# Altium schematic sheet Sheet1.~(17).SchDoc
size A4; SheetNumber: 1; SheetTotal: 1
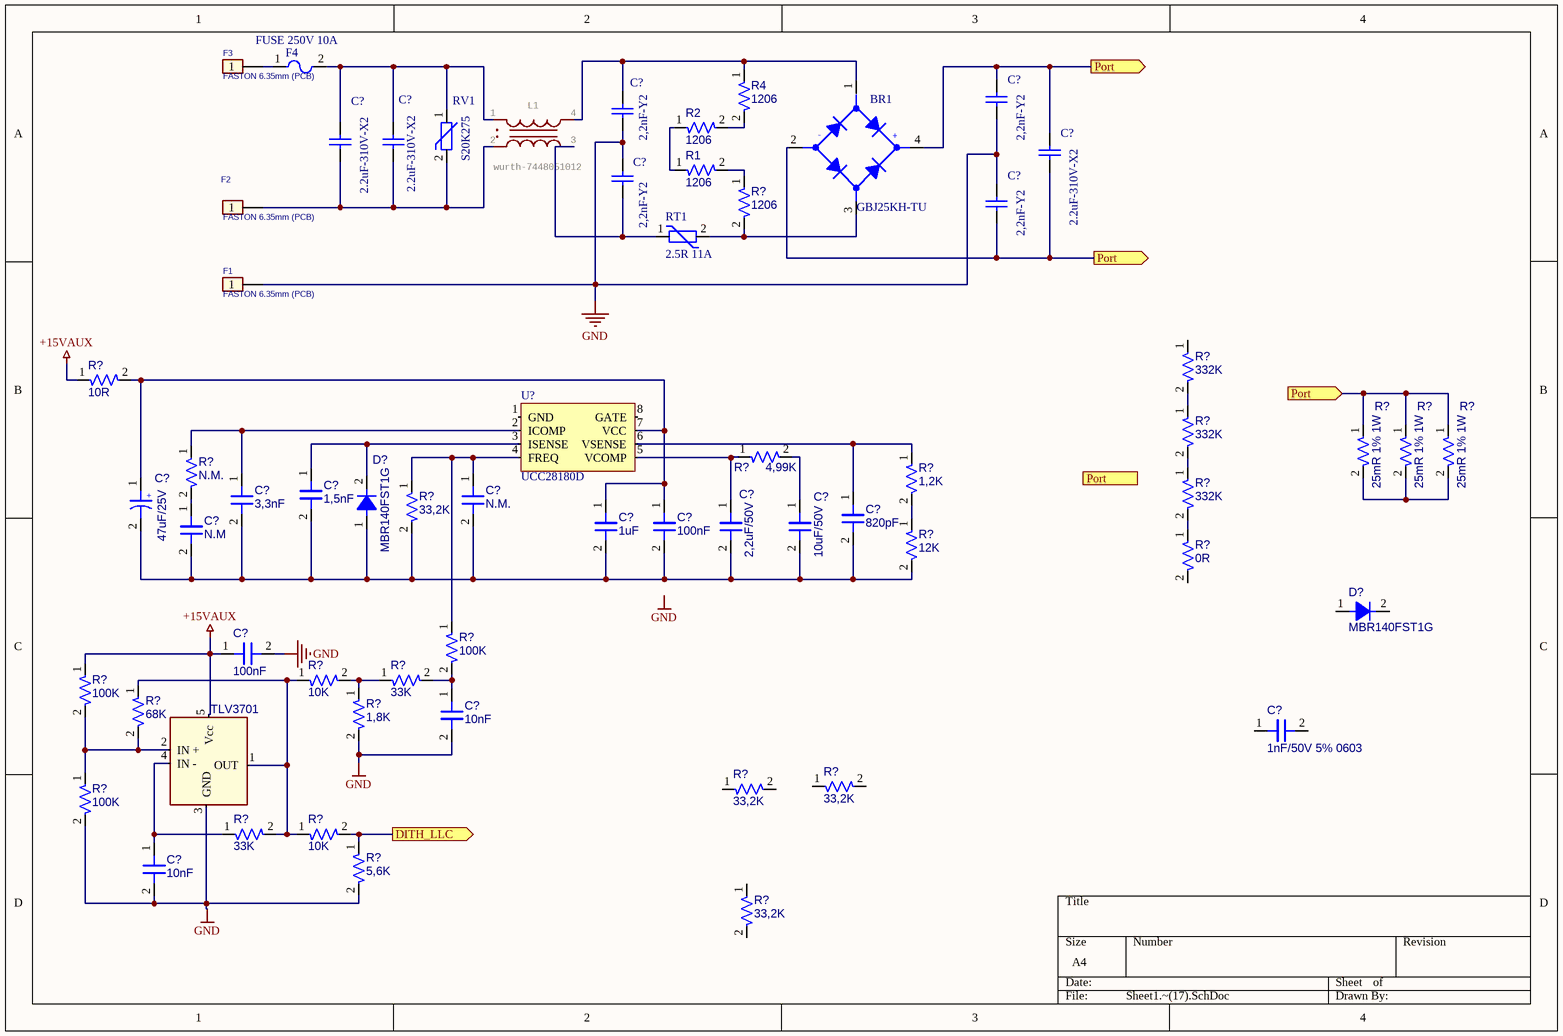
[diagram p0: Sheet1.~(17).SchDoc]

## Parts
(Parts that share a designator on the sheet are numbered #1, #2 ... from top to bottom, then left to right.)
BR1  GBJ25KH-TU
C?#1  2,2nF-Y2
C?#2  2,2nF-Y2
C?#3  2.2uF-310V-X2
C?#4  2.2uF-310V-X2
C?#5  2.2uF-310V-X2
C?#6  2,2nF-Y2
C?#7  2,2nF-Y2
C?#8  3,3nF  [0603N_CAP]
C?#9  1,5nF  [0603N_CAP]
C?#10  N.M.  [0603N_CAP]
C?#11  47uF/25V  [ELETTROLITICO_CASE_D]
C?#12  820pF  [0603N_CAP]
C?#13  1uF  [0603N_CAP]
C?#14  100nF  [0603N_CAP]
C?#15  2,2uF/50V  [1206_UP_CAP]
C?#16  10uF/50V  [1206_UP_CAP]
C?#17  N.M  [0603N_CAP]
C?#18  100nF  [0603N_CAP]
C?#19  10nF  [0603N_CAP]
C?#20  1nF/50V 5% 0603  [0603N_CAP]
C?#21  10nF  [0603N_CAP]
D?#1  MBR140FST1G
D?#2  MBR140FST1G
F1  FASTON 6.35mm (PCB)  [FASTON_M_PCB_6.35x0.81]
F2  FASTON 6.35mm (PCB)  [FASTON_M_PCB_6.35x0.81]
F3  FASTON 6.35mm (PCB)  [FASTON_M_PCB_6.35x0.81]
F4  FUSE 250V 10A
L1  wurth-7448051012  [WE-CMBNC_XL_7448051012]
R1  1206  [1206_UP_RES]
R2  1206  [1206_UP_RES]
R4  1206  [1206_UP_RES]
R?#1  1206  [1206_UP_RES]
R?#2  332K  [1206_UP_RES]
R?#3  10R  [1206_UP_RES]
R?#4  332K  [1206_UP_RES]
R?#5  25mR 1% 1W  [2512_up]
R?#6  25mR 1% 1W  [2512_up]
R?#7  25mR 1% 1W  [2512_up]
R?#8  N.M.  [0603N_RES]
R?#9  1,2K  [1206_UP_RES]
R?#10  4,99K  [0603N_RES]
R?#11  332K  [1206_UP_RES]
R?#12  33,2K  [0603N_RES]
R?#13  12K  [1206_UP_RES]
R?#14  0R  [1206_UP_RES]
R?#15  100K  [0603N_RES]
R?#16  100K  [0603N_RES]
R?#17  10K  [0603N_RES]
R?#18  33K  [0603N_RES]
R?#19  68K  [0603N_RES]
R?#20  1,8K  [0603N_RES]
R?#21  100K  [0603N_RES]
R?#22  33,2K  [0603N_RES]
R?#23  33,2K  [0603N_RES]
R?#24  33K  [0603N_RES]
R?#25  10K  [0603N_RES]
R?#26  5,6K  [0603N_RES]
R?#27  33,2K  [0603N_RES]
RT1  2.5R 11A
RV1  S20K275
TLV3701  TLV3701 SOT23-5L  [SOT-23 5PIN]  (value not drawn)
U?  UCC28180D  [SO8]

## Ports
DITH_LLC (out), Port (in), Port (out)

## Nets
+15VAUX: C?#18.1 R?#3.1 R?#16.1 TLV3701.5(Vcc)
GND: C?#1.1 C?#2.1 C?#6.2 C?#7.2 C?#18.2 C?#19.2 C?#21.2 F1.1 R?#20.2 R?#21.2 R?#26.2 TLV3701.3(GND)
DITH_LLC: R?#25.2 R?#26.1 ; port DITH_LLC
Port: BR1.2(-DC) BR1.4(+DC) C?#1.2 C?#5.1 C?#5.2 C?#7.1 R?#5.1 R?#6.1 R?#7.1 ; port Port
NetBR1_1: BR1.1(AC1) C?#2.2 L1.4 R4.1
NetBR1_3: BR1.3(AC2) R?#1.2 RT1.2
NetC?#3_1: C?#3.1 C?#4.1 F4.2 L1.1 RV1.1
NetC?#3_2: C?#3.2 C?#4.2 F2.1 L1.2 RV1.2
NetC?#6_1: C?#6.1 L1.3 RT1.1
NetC?#8_1: C?#8.1 R?#8.1 U?.2(ICOMP)
NetC?#8_2: C?#8.2 C?#9.2 C?#10.2 C?#11.2 C?#12.2 C?#13.2 C?#14.2 C?#15.2 C?#16.2 C?#17.2 D?#1.1 R?#12.2 R?#13.2
NetC?#9_1: C?#9.1 D?#1.2 U?.3(ISENSE)
NetC?#10_1: C?#10.1 R?#12.1 R?#15.1 U?.4(FREQ)
NetC?#11_1: C?#11.1 C?#13.1 C?#14.1 R?#3.2 U?.7(VCC)
NetC?#12_1: C?#12.1 R?#9.1 U?.6(VSENSE)
NetC?#15_1: C?#15.1 R?#10.1 U?.5(VCOMP)
NetC?#16_1: C?#16.1 R?#10.2
NetC?#17_1: C?#17.1 R?#8.2
NetC?#19_1: C?#19.1 R?#15.2 R?#18.2
NetC?#21_1: C?#21.1 R?#24.1 TLV3701.4(IN_-)
NetF3_1: F3.1 F4.1
NetR1_1: R1.1 R2.1
NetR1_2: R1.2 R?#1.1
NetR2_2: R2.2 R4.2
NetR?#2_2: R?#2.2 R?#4.1
NetR?#4_2: R?#4.2 R?#11.1
NetR?#5_2: R?#5.2 R?#6.2 R?#7.2
NetR?#9_2: R?#9.2 R?#13.1
NetR?#11_2: R?#11.2 R?#14.1
NetR?#16_2: R?#16.2 R?#19.2 R?#21.1 TLV3701.2(IN_+)
NetR?#17_1: R?#17.1 R?#19.1 R?#24.2 R?#25.1 TLV3701.1(OUT)
NetR?#17_2: R?#17.2 R?#18.1 R?#20.1

Not connected (* = marked no-connect by the designer): C?#20 1 2; D?#2 1 2; R?#2 1; R?#14 2; R?#22 1 2; R?#23 1 2; R?#27 1 2; U? 1(GND) 8(GATE)

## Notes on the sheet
- Labels drawn without touching a wire or pin: GND

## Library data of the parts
BR1 = BRIDGE_D15XB60_15A_600V: BRIDGE DIOTEC GBJ25KH-TU 25A 800V; Costo: 0; Aggiornato: NO
C?#1 C?#2 C?#6 C?#7 = Cap: 2,2nF-Y2-300V MURATA DE6E3KJ222MA4B; Value: 2,2nF
C?#3-C?#5 = Cap: 2.2uF-310V-X2  VISHAY F339M/52231MIM2T0; Value: 2,2uF
C?#8-C?#10 C?#12-C?#14 C?#17-C?#19 C?#21 = CAP_NP_1nF_50V_5%_0603: 1nF/50V 5% 0603; Aggiornato: S; Costo: 0,01; Value: 1n; ContoLavoro: 0
C?#11 = CAP_P_47uF_50V_CASE_D: 47uF/50V FK SMD CASE D; Aggiornato: SI; Costo: 0,292; Value: 47u; ContoLavoro: 0
C?#15 C?#16 = CAP_NP_10uF_50V_1206_10%: CAP NP 10uF 50V 1206; Costo: 0,15; Aggiornato: S; Value: 10u; ContoLavoro: 0
C?#20 = CAP_NP_1nF_50V_5%_0603: Aggiornato: S; Costo: 0,01; Value: 1n; ContoLavoro: 0
D?#1 D?#2 = D_LL4148: ON SEMICUNDUCTOR, Schottky Power Rectifier, 1.0 A, 40 V, SOD-123FL; Aggiornato: SI; ContoLavoro: 0
F1-F3 = FASTON_M_PCB_6.35mm: FASTON M PCB 6.35mm; Hpcode: FASTMASCSTAMP; Costo: 0,01; Aggiornato: s; ContoLavoro: 0
F4 = FUSE_250V_6.3A_T_BEL_FUSE_0697A6300-01: PORTAFUIBILE DA C.S.  250Vac 10A 6,3x32; Aggiornato: S; ContoLavoro: 0
L1 = WE-CMBNC_XL_7448051012: GateName_1: G$1; IR: 10A; RDC: 15mOhm; VR: 250  V (AC); VT: 1500  V (AC)
R1 R2 R4 R?#1 R?#3 R?#9 R?#13 R?#14 = R_0.33_1%_1206: 1206 SMD RESISTOR; Aggiornato: s; ContoLavoro: 0
R?#2 R?#4 R?#11 = R_0.33_1%_1206: 1206 0,1% SMD RESISTOR; Aggiornato: s; ContoLavoro: 0
R?#5-R?#7 = R_0.5R_1%_2512: 25mOhm 1% 2512 1W WSL SMD RESISTOR; Costo: 0,40; Value: 0,025; Aggiornato: s; ContoLavoro: 0
R?#8 R?#10 R?#12 R?#15-R?#27 = R_0R_1%_0603: 0R 1% 0603 SMD RESISTOR; Costo: 0,00073; Value: 0; Aggiornato: S
RT1 = RT_2.5R_10A: NTC 2.5R 11A  TDK B57364S0259M0 21x7; Costo: 0; Aggiornato: NO
RV1 = VARISTOR: VARISTORE TDK S20K275 B72220S0271K101; Aggiornato: NO; ContoLavoro: 0
TLV3701 = TLV3701 SOT23-5L: Costo: 0; DeviceFunction: Voltage Regulator; Aggiornato: NO
U? = UCC28180D: Costo: 1,534; Aggiornato: NO; ContoLavoro: 0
